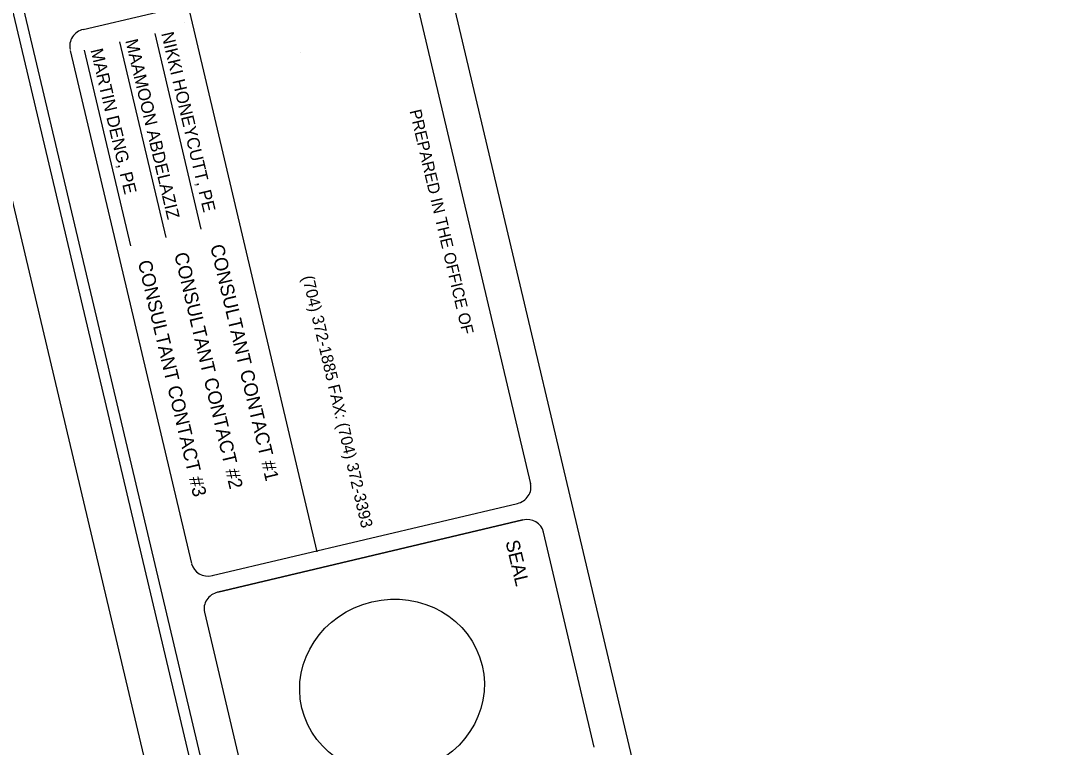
# Model space of a CAD drawing. Extents: x 1439200 to 1640973, y 392611 to 606444.
# Drawn here: x 1440332 to 1442416, y 599535 to 600981 of the extents above; entities that cross this region are included whole.
import ezdxf

# ---------------------------------------------------------------- set-up
doc = ezdxf.new("R2010")
doc.units = 0
doc.layers.add('Level 43', color=7, linetype='Continuous')
doc.layers.add('Old_Level_20', color=7, linetype='Continuous')

msp = doc.modelspace()

# ---------------------------------------------------------------- linework, layer by layer
at = {"layer": 'Level 43'}
for p, q in [((1440363.8, 604519.2), (1441803.1, 598439.2)), ((1440456, 600964.1), (1441063.7, 601107.2)), ((1441105, 601083.4), (1441347.1, 600059.3)), ((1440664.9, 601010.8), (1440921.4, 599923.4)), ((1440658, 600977.6), (1440658, 600977.6)), ((1440528.1, 600939.2), (1440620.2, 600550)), ((1440598.2, 600955.8), (1440690.3, 600566.6)), ((1440430, 600922.1), (1440671.6, 599900.3)), ((1440457.9, 600922.6), (1440550.1, 600533.4)), ((1440888.2, 600919.1), (1440888.2, 600919.1)), ((1440713, 599876.3), (1441321, 600020.2)), ((1441332, 599987.1), (1440724, 599843.3)), ((1440724, 599843.3), (1441332, 599987.1)), ((1441332, 599987.1), (1440724, 599843.3)), ((1441372.2, 599962.8), (1441473.3, 599534.8)), ((1440697.6, 599803.4), (1440798.6, 599373.6))]:
    msp.add_line(p, q, dxfattribs=at)
msp.add_lwpolyline([(1445632.9, 599164.9), (1443909.8, 606443.8), (1439200, 605328.8), (1440923.1, 598050)], close=True, dxfattribs=at)
msp.add_lwpolyline([(1439494.5, 604562.1), (1440994.6, 598225.2)], dxfattribs=at)
for centre, major_axis, ratio, start_param, end_param in [((1440463.5, 600932.3), (33.8, 8), 0.941469, 1.570198, 3.141359), ((1441313.5, 600051.5), (33.8, 8), 0.930867, 4.711814, 6.283034), ((1441339.3, 599955.1), (33.8, 8), 0.941469, 6.283006, 7.85338), ((1440705.7, 599908), (-33.8, -8), 0.941469, 6.282951, 7.853377), ((1440731.2, 599811.3), (-33.8, -8), 0.941469, 4.711788, 6.282949)]:
    msp.add_ellipse(centre, major_axis=major_axis, ratio=ratio, start_param=start_param, end_param=end_param, dxfattribs=at)
msp.add_ellipse((1441071.2, 599655), major_axis=(-179.6, -42.5), ratio=0.941469, dxfattribs=at)
at = {"layer": 'Old_Level_20'}
msp.add_lwpolyline([(1439298.8, 605293.4), (1440988.4, 598155.9), (1445527, 599230.3), (1443837.3, 606367.8)], close=True, dxfattribs=at)

# ---------------------------------------------------------------- texts
at = {"layer": 'Level 43'}
for s, height, p in [('NIKKI HONEYCUTT, PE', 25, (1440611.1, 600956.2)), ('MAAMOON ABDELAZIZ', 25, (1440539.5, 600942)), ('MARTIN DENG, PE', 25, (1440470.1, 600923.2)), ('PREPARED IN THE OFFICE OF', 23.423, (1441106, 600801.9)), ('CONSULTANT CONTACT #2', 27.199, (1440637, 600516.8)), ('CONSULTANT CONTACT #1', 27.199, (1440708.7, 600532.7)), ('CONSULTANT CONTACT #3', 27.199, (1440564.5, 600501.2)), ('(704) 372-1885 FAX: (704) 372-3393', 23.423, (1440892.1, 600471)), ('SEAL ', 27.2, (1441297.1, 599943.8))]:
    msp.add_text(s, height=height, rotation=283.3038, dxfattribs=at).set_placement(p)

doc.saveas('drawing.dxf')
